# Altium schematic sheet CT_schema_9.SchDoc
size 391 x 238 mm
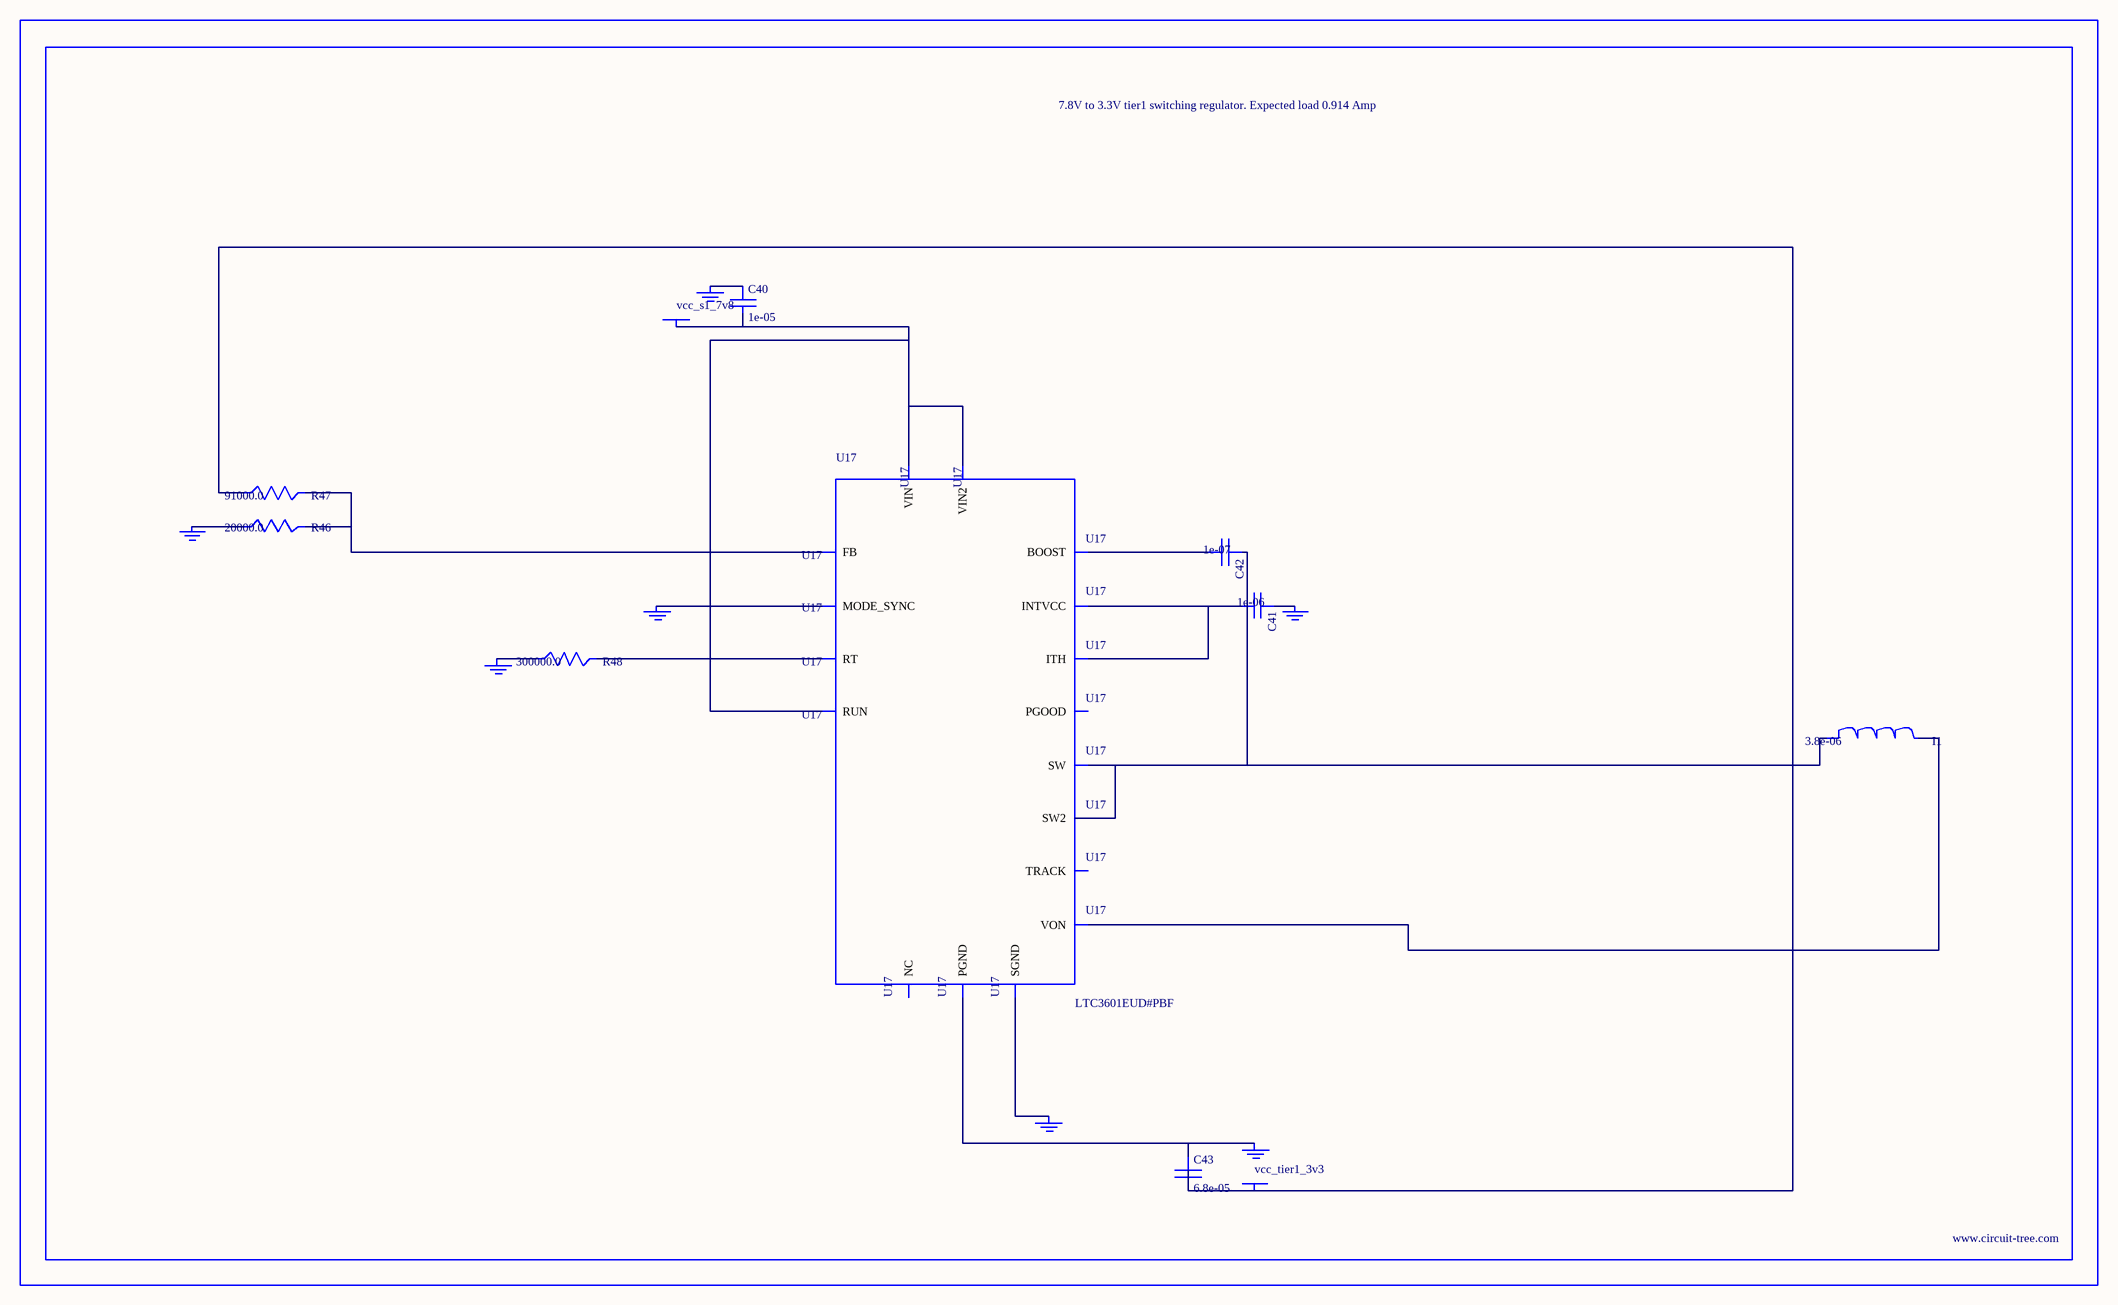
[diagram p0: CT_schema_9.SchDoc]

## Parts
BORDER8  (no value)
C40  1e-05  [C0805]
C41  1e-06  [C0603]
C42  1e-07  [C0402]
C43  6.8e-05  [2220]
GND_INSTANCE_8_0  (no value)
GND_INSTANCE_8_1  (no value)
GND_INSTANCE_8_2  (no value)
GND_INSTANCE_8_3  (no value)
GND_INSTANCE_8_4  (no value)
GND_INSTANCE_8_5  (no value)
GND_INSTANCE_8_6  (no value)
I1  3.8e-06  [DR1040]
POWER_INSTANCE_8_0  vcc_s1_7v8
POWER_INSTANCE_8_1  vcc_tier1_3v3
R46  20000.0  [R0603]
R47  91000.0  [R0603]
R48  300000.0  [R0603]
U17  LTC3601EUD#PBF  [QFN-16_EP]

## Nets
NetC40_1: C40.1 GND_INSTANCE_8_5.0(GND)
NetC40_2: C40.2 POWER_INSTANCE_8_0.0(PWR) U17.14(RUN) U17.15(VIN) U17.16(VIN2)
NetC41_1: C41.1 GND_INSTANCE_8_1.0(GND)
NetC41_2: C41.2 U17.7(INTVCC) U17.12(ITH)
NetC42_1: C42.1 I1.1 U17.3(SW) U17.4(SW2)
NetC42_2: C42.2 U17.6(BOOST)
NetC43_1: C43.1 GND_INSTANCE_8_6.0(GND) U17.17(PGND)
NetC43_2: C43.2 I1.2 POWER_INSTANCE_8_1.0(PWR) R47.1 U17.8(VON)
NetGND_INSTANCE_8_0_0: GND_INSTANCE_8_0.0(GND) U17.1(MODE_SYNC)
NetGND_INSTANCE_8_2_0: GND_INSTANCE_8_2.0(GND) U17.9(SGND)
NetGND_INSTANCE_8_3_0: GND_INSTANCE_8_3.0(GND) R48.1
NetGND_INSTANCE_8_4_0: GND_INSTANCE_8_4.0(GND) R46.1
NetR46_2: R46.2 R47.2 U17.11(FB)
NetR48_2: R48.2 U17.10(RT)

Not connected (* = marked no-connect by the designer): U17 2(PGOOD) 5(NC) 13(TRACK)

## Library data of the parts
BORDER8 = BORDER_PAGE8
C40 = C0805C106K8RACTU
C41 = C0603C105K3RACTU
C42 = C0402C104K3RACTU
C43 = C5750X5R1A686M
GND_INSTANCE_8_0-GND_INSTANCE_8_6 = GND
I1 = DR1040-3R8-R
POWER_INSTANCE_8_0 POWER_INSTANCE_8_1 = PWR
R46 = RC0603JR-0720KL
R47 = RC0603JR-0791KL
R48 = RC0603JR-07300KL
